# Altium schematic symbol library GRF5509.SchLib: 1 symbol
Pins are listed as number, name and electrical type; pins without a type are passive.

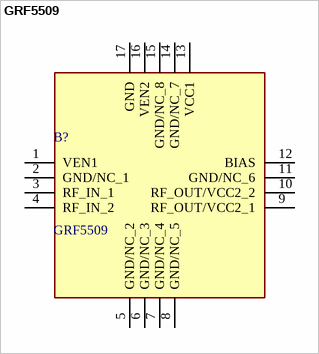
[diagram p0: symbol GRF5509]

## GRF5509
designator B?
RF Amplifier High Efficiency, 5.0Watt PA/Saturated PA, OP1dB >34.0 dBm, 900 MHz ISM; 0.7 - 01.8 GHz; Manufacturer_Name: Guerrilla RF; Geometry.Height: 0.85mm
footprint QFN50P300X300X85-17N
pins: 1 VEN1, 2 GND/NC_1, 3 RF_IN_1, 4 RF_IN_2, 5 GND/NC_2, 6 GND/NC_3, 7 GND/NC_4, 8 GND/NC_5, 9 RF_OUT/VCC2_1, 10 RF_OUT/VCC2_2, 11 GND/NC_6, 12 BIAS, 13 VCC1, 14 GND/NC_7, 15 GND/NC_8, 16 VEN2, 17 GND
